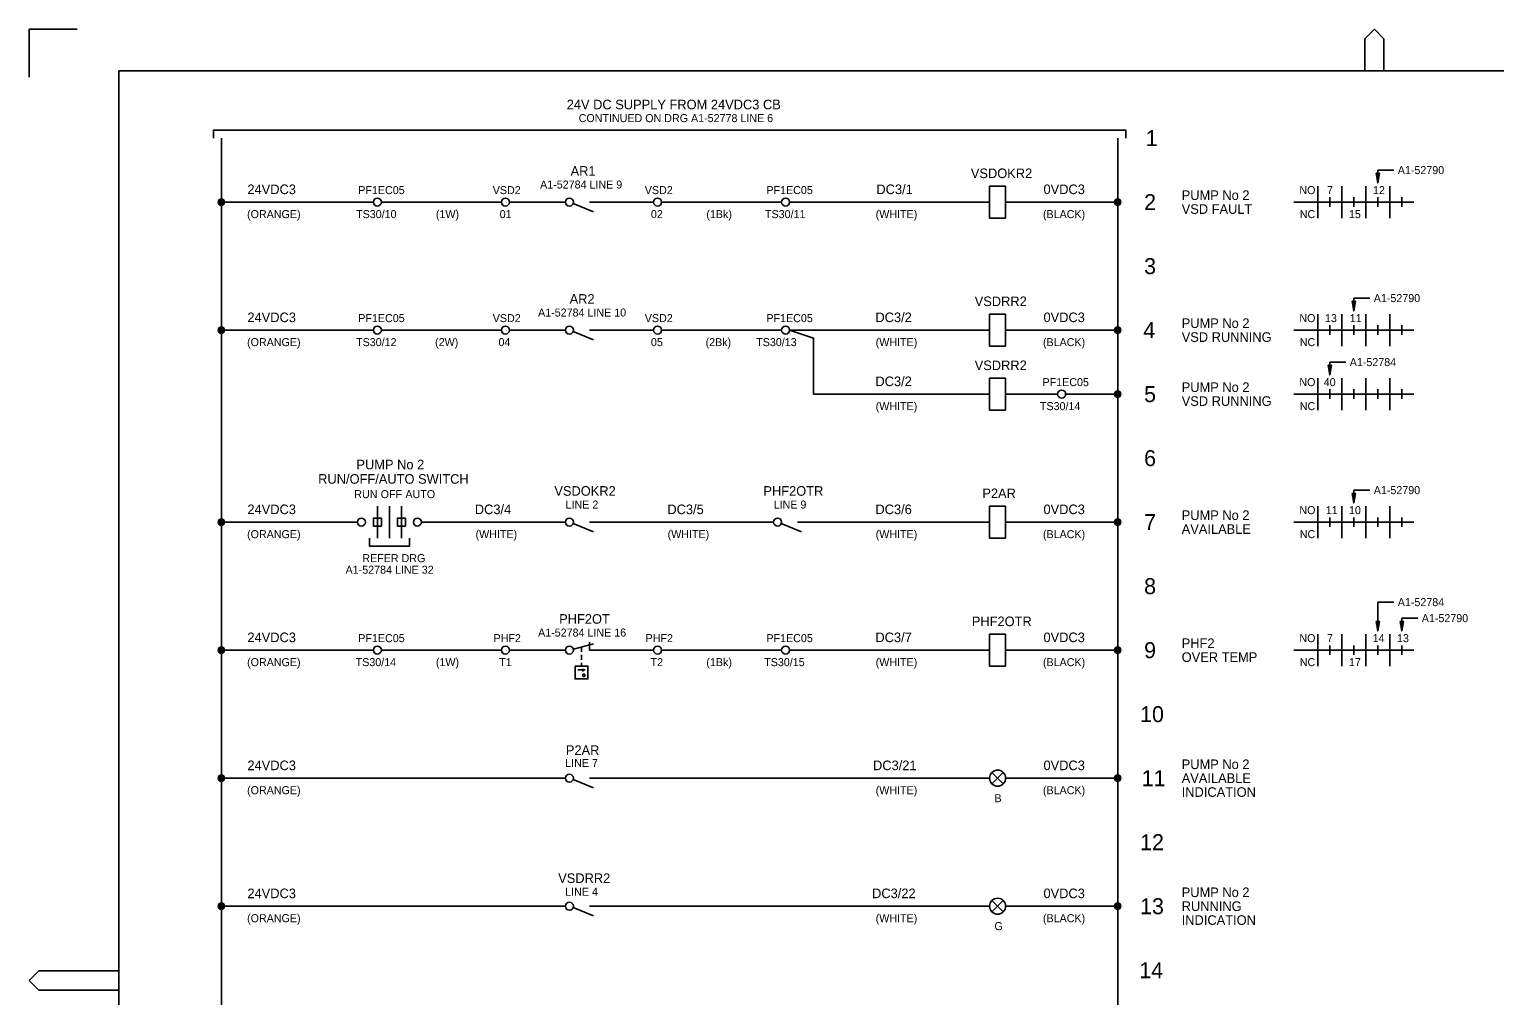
# Model space of a CAD drawing. Extents: x 0 to 841, y 0 to 594.
# Drawn here: x 0 to 457.8, y 292 to 594 of the extents above; entities that cross this region are included whole.
import ezdxf

# ---------------------------------------------------------------- set-up
doc = ezdxf.new("R2010")
doc.units = 0
for name, color, linetype in [('A1BORDER', 7, 'Continuous'), ('Level 1', 7, 'Continuous'), ('Level 10', 7, 'Continuous'), ('Level 5', 7, 'Continuous'), ('Level 6', 7, 'Continuous')]:
    doc.layers.add(name, color=color, linetype=linetype)

msp = doc.modelspace()

# ---------------------------------------------------------------- linework, layer by layer
at = {"layer": 'A1BORDER'}
for p, q in [((0, 594), (15, 594)), ((0, 579), (0, 594)), ((417.19, 591), (420.19, 594)), ((417.19, 581), (417.19, 591)), ((423.19, 591), (420.19, 594)), ((423.19, 581), (423.19, 591)), ((28, 581), (829, 581)), ((28, 581), (28, 15)), ((3, 299.76), (0, 296.76)), ((28, 299.76), (3, 299.76)), ((3, 293.76), (0, 296.76)), ((28, 293.76), (3, 293.76))]:
    msp.add_line(p, q, dxfattribs=at)
at = {"layer": 'Level 1'}
for p, q in [((60, 200), (60, 560)), ((340, 200), (340, 560)), ((402.5, 535), (402.5, 545)), ((410, 535), (410, 545)), ((417.5, 535), (417.5, 545)), ((425, 535), (425, 545)), ((406.25, 541.5), (406.25, 538.5)), ((413.75, 541.5), (413.75, 538.5)), ((421.25, 541.5), (421.25, 538.5)), ((428.75, 541.5), (428.75, 538.5)), ((60, 540), (107.5, 540)), ((147.5, 540), (110, 540)), ((167.5, 540), (150, 540)), ((167.5, 540), (167.5, 540)), ((175, 540), (177.5, 540)), ((177.5, 540), (177.5, 540)), ((195, 540), (177.5, 540)), ((235, 540), (197.5, 540)), ((305, 540), (340, 540)), ((395, 540), (432.5, 540)), ((402.5, 495), (402.5, 505)), ((410, 495), (410, 505)), ((417.5, 495), (417.5, 505)), ((425, 495), (425, 505)), ((60, 500), (107.5, 500)), ((147.5, 500), (110, 500)), ((167.5, 500), (150, 500)), ((167.5, 500), (167.5, 500)), ((175, 500), (177.5, 500)), ((177.5, 500), (177.5, 500)), ((195, 500), (177.5, 500)), ((235, 500), (197.5, 500)), ((305, 500), (340, 500)), ((395, 500), (432.5, 500)), ((406.25, 501.5), (406.25, 498.5)), ((413.75, 501.5), (413.75, 498.5)), ((421.25, 501.5), (421.25, 498.5)), ((428.75, 501.5), (428.75, 498.5)), ((402.5, 475), (402.5, 485)), ((406.25, 481.5), (406.25, 478.5)), ((410, 475), (410, 485)), ((413.75, 481.5), (413.75, 478.5)), ((417.5, 475), (417.5, 485)), ((421.25, 481.5), (421.25, 478.5)), ((425, 475), (425, 485)), ((428.75, 481.5), (428.75, 478.5)), ((321.25, 480), (305, 480)), ((323.75, 480), (340, 480)), ((395, 480), (432.5, 480)), ((108.75, 445), (108.75, 435)), ((112.5, 445), (112.5, 435)), ((116.25, 445), (116.25, 435)), ((402.5, 435), (402.5, 445)), ((410, 435), (410, 445)), ((417.5, 435), (417.5, 445)), ((425, 435), (425, 445)), ((102.5, 440), (60, 440)), ((167.5, 440), (122.5, 440)), ((167.5, 440), (167.5, 440)), ((175, 440), (177.5, 440)), ((232.5, 440), (177.5, 440)), ((177.5, 440), (177.5, 440)), ((232.5, 440), (232.5, 440)), ((240, 440), (242.5, 440)), ((242.5, 440), (242.5, 440)), ((305, 440), (340, 440)), ((395, 440), (432.5, 440)), ((406.25, 441.5), (406.25, 438.5)), ((413.75, 441.5), (413.75, 438.5)), ((421.25, 441.5), (421.25, 438.5)), ((428.75, 441.5), (428.75, 438.5)), ((402.5, 395), (402.5, 405)), ((410, 395), (410, 405)), ((417.5, 395), (417.5, 405)), ((425, 395), (425, 405)), ((60, 400), (107.5, 400)), ((147.5, 400), (110, 400)), ((167.5, 400), (150, 400)), ((167.5, 400), (167.5, 400)), ((172.5, 401), (172.5, 399.5)), ((172.5, 398.5), (172.5, 397)), ((175, 400), (177.5, 400)), ((195, 400), (177.5, 400)), ((177.5, 400), (177.5, 400)), ((235, 400), (197.5, 400)), ((305, 400), (340, 400)), ((395, 400), (432.5, 400)), ((406.25, 401.5), (406.25, 398.5)), ((413.75, 401.5), (413.75, 398.5)), ((421.25, 401.5), (421.25, 398.5)), ((428.75, 401.5), (428.75, 398.5)), ((172.5, 396), (172.5, 395)), ((60, 360), (167.5, 360)), ((167.5, 360), (167.5, 360)), ((175, 360), (177.5, 360)), ((177.5, 360), (177.5, 360)), ((305, 360), (340, 360)), ((60, 320), (167.5, 320)), ((167.5, 320), (167.5, 320)), ((175, 320), (177.5, 320)), ((177.5, 320), (177.5, 320)), ((305, 320), (340, 320))]:
    msp.add_line(p, q, dxfattribs=at)
for points in [[(57.5, 560), (57.5, 562.5), (342.5, 562.5), (342.5, 560)], [(237.5, 500), (245, 497.5), (245, 480), (300, 480)], [(106.25, 435), (106.25, 432.5), (118.75, 432.5), (118.75, 435)], [(173.63, 393.87), (171.37, 393.87)], [(172.88, 394.12), (172.88, 393.37)], [(172.88, 392.14), (172.92, 392.32), (173.06, 392.45), (173.26, 392.51), (173.44, 392.45), (173.57, 392.32), (173.63, 392.14), (173.57, 391.94), (173.44, 391.8), (173.26, 391.76), (173.06, 391.8), (172.92, 391.94), (172.88, 392.14)]]:
    msp.add_lwpolyline(points, dxfattribs=at)
for points in [[(107.5, 438.75), (110, 438.75), (110, 441.25), (107.5, 441.25)], [(115, 438.75), (117.5, 438.75), (117.5, 441.25), (115, 441.25)], [(170.5, 395), (170.5, 391), (174.5, 391), (174.5, 395)]]:
    msp.add_lwpolyline(points, close=True, dxfattribs=at)
at = {"layer": 'Level 10'}
for p, q in [((59.1, 540.44), (59.1, 539.56)), ((59.4, 540.8), (59.4, 539.2)), ((59.7, 540.95), (59.7, 539.05)), ((60, 541), (60, 539.01)), ((60.3, 540.95), (60.3, 539.05)), ((60.6, 540.8), (60.6, 539.2)), ((60.9, 540.44), (60.9, 539.56)), ((339.1, 540.44), (339.1, 539.56)), ((339.4, 540.8), (339.4, 539.2)), ((339.7, 540.95), (339.7, 539.05)), ((340, 541), (340, 539.01)), ((340.3, 540.95), (340.3, 539.05)), ((340.6, 540.8), (340.6, 539.2)), ((340.9, 540.44), (340.9, 539.56)), ((61, 540), (61, 540)), ((169.91, 539.54), (176.25, 537)), ((341, 540), (341, 540)), ((59.1, 500.44), (59.1, 499.56)), ((59.4, 500.8), (59.4, 499.2)), ((59.7, 500.95), (59.7, 499.05)), ((60, 501), (60, 499.01)), ((60.3, 500.95), (60.3, 499.05)), ((60.6, 500.8), (60.6, 499.2)), ((60.9, 500.44), (60.9, 499.56)), ((61, 500), (61, 500)), ((169.91, 499.54), (176.25, 497)), ((339.1, 500.44), (339.1, 499.56)), ((339.4, 500.8), (339.4, 499.2)), ((339.7, 500.95), (339.7, 499.05)), ((340, 501), (340, 499.01)), ((340.3, 500.95), (340.3, 499.05)), ((340.6, 500.8), (340.6, 499.2)), ((340.9, 500.44), (340.9, 499.56)), ((341, 500), (341, 500)), ((339.4, 480.8), (339.4, 479.2)), ((339.7, 480.95), (339.7, 479.05)), ((340, 481), (340, 479.01)), ((340.3, 480.95), (340.3, 479.05)), ((340.6, 480.8), (340.6, 479.2)), ((339.1, 480.44), (339.1, 479.56)), ((340.9, 480.44), (340.9, 479.56)), ((341, 480), (341, 480)), ((59.1, 440.44), (59.1, 439.56)), ((59.4, 440.8), (59.4, 439.2)), ((59.7, 440.95), (59.7, 439.05)), ((60, 441), (60, 439.01)), ((60.3, 440.95), (60.3, 439.05)), ((60.6, 440.8), (60.6, 439.2)), ((60.9, 440.44), (60.9, 439.56)), ((61, 440), (61, 440)), ((169.91, 439.54), (176.25, 437)), ((234.91, 439.54), (241.25, 437)), ((339.1, 440.44), (339.1, 439.56)), ((339.4, 440.8), (339.4, 439.2)), ((339.7, 440.95), (339.7, 439.05)), ((340, 441), (340, 439.01)), ((340.3, 440.95), (340.3, 439.05)), ((340.6, 440.8), (340.6, 439.2)), ((340.9, 440.44), (340.9, 439.56)), ((341, 440), (341, 440)), ((59.1, 400.44), (59.1, 399.56)), ((59.4, 400.8), (59.4, 399.2)), ((59.7, 400.95), (59.7, 399.05)), ((60, 401), (60, 399.01)), ((60.3, 400.95), (60.3, 399.05)), ((60.6, 400.8), (60.6, 399.2)), ((60.9, 400.44), (60.9, 399.56)), ((61, 400), (61, 400)), ((169.96, 400.32), (176.25, 402)), ((175, 402.5), (175, 400)), ((339.1, 400.44), (339.1, 399.56)), ((339.4, 400.8), (339.4, 399.2)), ((339.7, 400.95), (339.7, 399.05)), ((340, 401), (340, 399.01)), ((340.3, 400.95), (340.3, 399.05)), ((340.6, 400.8), (340.6, 399.2)), ((340.9, 400.44), (340.9, 399.56)), ((341, 400), (341, 400)), ((304.27, 361.77), (300.73, 358.23)), ((300.73, 361.77), (304.27, 358.23)), ((59.1, 360.44), (59.1, 359.56)), ((59.4, 360.8), (59.4, 359.2)), ((59.7, 360.95), (59.7, 359.05)), ((60, 361), (60, 359.01)), ((60.3, 360.95), (60.3, 359.05)), ((60.6, 360.8), (60.6, 359.2)), ((60.9, 360.44), (60.9, 359.56)), ((61, 360), (61, 360)), ((169.91, 359.54), (176.25, 357)), ((339.1, 360.44), (339.1, 359.56)), ((339.4, 360.8), (339.4, 359.2)), ((339.7, 360.95), (339.7, 359.05)), ((340, 361), (340, 359.01)), ((340.3, 360.95), (340.3, 359.05)), ((340.6, 360.8), (340.6, 359.2)), ((340.9, 360.44), (340.9, 359.56)), ((341, 360), (341, 360)), ((59.4, 320.8), (59.4, 319.2)), ((59.7, 320.95), (59.7, 319.05)), ((60, 321), (60, 319.01)), ((60.3, 320.95), (60.3, 319.05)), ((60.6, 320.8), (60.6, 319.2)), ((304.27, 321.77), (300.73, 318.23)), ((300.73, 321.77), (304.27, 318.23)), ((339.4, 320.8), (339.4, 319.2)), ((339.7, 320.95), (339.7, 319.05)), ((340, 321), (340, 319.01)), ((340.3, 320.95), (340.3, 319.05)), ((340.6, 320.8), (340.6, 319.2)), ((59.1, 320.44), (59.1, 319.56)), ((60.9, 320.44), (60.9, 319.56)), ((61, 320), (61, 320)), ((169.91, 319.54), (176.25, 317)), ((339.1, 320.44), (339.1, 319.56)), ((340.9, 320.44), (340.9, 319.56)), ((341, 320), (341, 320))]:
    msp.add_line(p, q, dxfattribs=at)
for points in [[(305, 545), (305, 535), (300, 535), (300, 545), (305, 545)], [(305, 505), (305, 495), (300, 495), (300, 505), (305, 505)], [(305, 485), (305, 475), (300, 475), (300, 485), (305, 485)], [(305, 445), (305, 435), (300, 435), (300, 445), (305, 445)], [(305, 405), (305, 395), (300, 395), (300, 405), (305, 405)]]:
    msp.add_lwpolyline(points, dxfattribs=at)
for centre, radius in [((60, 540), 1), ((168.75, 540), 1.25), ((340, 540), 1), ((60, 500), 1), ((168.75, 500), 1.25), ((340, 500), 1), ((340, 480), 1), ((60, 440), 1), ((168.75, 440), 1.25), ((233.75, 440), 1.25), ((340, 440), 1), ((60, 400), 1), ((168.75, 400), 1.25), ((340, 400), 1), ((302.5, 360), 2.5), ((60, 360), 1), ((168.75, 360), 1.25), ((340, 360), 1), ((60, 320), 1), ((168.75, 320), 1.25), ((302.5, 320), 2.5), ((340, 320), 1)]:
    msp.add_circle(centre, radius, dxfattribs=at)
at = {"layer": 'Level 5'}
for centre in [(108.75, 540), (148.75, 540), (196.25, 540), (236.25, 540), (108.75, 500), (148.75, 500), (196.25, 500), (236.25, 500), (322.5, 480), (103.75, 440), (121.25, 440), (108.75, 400), (148.75, 400), (196.25, 400), (236.25, 400)]:
    msp.add_circle(centre, 1.25, dxfattribs=at)
at = {"layer": 'Level 6'}
for p, q in [((421.25, 546.5), (421.25, 550)), ((421.25, 550), (426.25, 550)), ((237.5, 540), (300, 540)), ((413.75, 506.5), (413.75, 510)), ((413.75, 510), (418.75, 510)), ((237.5, 500), (300, 500)), ((406.25, 486.5), (406.25, 490)), ((406.25, 490), (411.25, 490)), ((413.75, 446.5), (413.75, 450)), ((413.75, 450), (418.75, 450)), ((242.5, 440), (300, 440)), ((421.25, 406.5), (421.25, 415)), ((421.25, 415), (426.25, 415)), ((428.75, 406.5), (428.75, 410)), ((428.75, 410), (433.75, 410)), ((237.5, 400), (300, 400)), ((177.5, 360), (300, 360)), ((177.5, 320), (300, 320))]:
    msp.add_line(p, q, dxfattribs=at)
for points in [[(420.75, 549), (421.25, 546), (421.75, 549)], [(413.25, 509), (413.75, 506), (414.25, 509)], [(405.75, 489), (406.25, 486), (406.75, 489)], [(413.25, 449), (413.75, 446), (414.25, 449)], [(420.75, 409), (421.25, 406), (421.75, 409)], [(428.25, 409), (428.75, 406), (429.25, 409)]]:
    msp.add_lwpolyline(points, close=True, dxfattribs=at)

# ---------------------------------------------------------------- texts
at = {"layer": 'Level 1'}
for s, height, p in [('24V DC SUPPLY FROM 24VDC3 CB', 3, (167.88, 569)), ('CONTINUED ON DRG A1-52778 LINE 6', 2.5, (171.61, 565)), ('1', 5, (348.75, 557.5)), ('PF1EC05', 2.5, (102.77, 542.5)), ('VSD2', 2.5, (144.77, 542.5)), ('VSD2', 2.5, (192.27, 542.5)), ('PF1EC05', 2.5, (230.27, 542.5)), ('NO', 2.5, (396.76, 542.5)), ('7', 2.5, (405.38, 542.5)), ('12', 2.5, (419.76, 542.5)), ('2', 5, (348.26, 537.5)), ('NC', 2.5, (396.88, 535)), ('15', 2.5, (412.26, 535)), ('3', 5, (348.26, 517.5)), ('PF1EC05', 2.5, (102.77, 502.5)), ('VSD2', 2.5, (144.77, 502.5)), ('VSD2', 2.5, (192.27, 502.5)), ('PF1EC05', 2.5, (230.27, 502.5)), ('NO', 2.5, (396.76, 502.5)), ('13', 2.5, (404.76, 502.5)), ('11', 2.5, (412.5, 502.5)), ('4', 5, (348.01, 497.5)), ('NC', 2.5, (396.88, 495)), ('PF1EC05', 2.5, (316.52, 482.5)), ('5', 5, (348.26, 477.5)), ('NO', 2.5, (396.76, 482.5)), ('40', 2.5, (404.38, 482.5)), ('NC', 2.5, (396.88, 475)), ('6', 5, (348.26, 457.5)), ('PUMP No 2', 3, (102.19, 456.5)), ('RUN/OFF/AUTO SWITCH', 3, (90.24, 452)), ('RUN', 2.5, (101.52, 447.5)), ('OFF', 2.5, (109.76, 447.5)), ('AUTO', 2.5, (117.5, 447.5)), ('NO', 2.5, (396.76, 442.5)), ('11', 2.5, (405.01, 442.5)), ('10', 2.5, (412.26, 442.5)), ('7', 5, (348.26, 437.5)), ('NC', 2.5, (396.88, 435)), ('A1-52784 LINE 32', 2.5, (98.8, 423.88)), ('REFER DRG', 2.5, (104.03, 427.5)), ('8', 5, (348.26, 417.5)), ('PF1EC05', 2.5, (102.77, 402.5)), ('PHF2', 2.5, (145.02, 402.5)), ('PHF2', 2.5, (192.52, 402.5)), ('PF1EC05', 2.5, (230.27, 402.5)), ('NO', 2.5, (396.76, 402.5)), ('7', 2.5, (405.38, 402.5)), ('14', 2.5, (419.63, 402.5)), ('13', 2.5, (427.26, 402.5)), ('9', 5, (348.26, 397.5)), ('NC', 2.5, (396.88, 395)), ('17', 2.5, (412.26, 395)), ('10', 5, (347.01, 377.5)), ('11', 5, (347.51, 357.5)), ('12', 5, (347.01, 337.5)), ('13', 5, (347.01, 317.5)), ('14', 5, (346.76, 297.5))]:
    msp.add_text(s, height=height, dxfattribs=at).set_placement(p)
at = {"layer": 'Level 5'}
for s, height, p in [('AR1', 3, (169.1, 548.25)), ('VSDOKR2', 3, (294.13, 547.5)), ('A1-52790', 2.5, (427.5, 548.75)), ('24VDC3', 3, (68.13, 542.5)), ('A1-52784 LINE 9', 2.5, (159.57, 544.25)), ('DC3/1', 3, (264.62, 542.5)), ('0VDC3', 3, (316.82, 542.5)), ('PUMP No 2', 3, (360, 540.67)), ('(ORANGE)', 2.5, (68.03, 535)), ('TS30/10', 2.5, (102.08, 535)), ('(1W)', 2.5, (127.01, 535)), ('01', 2.5, (146.94, 535)), ('02', 2.5, (194.19, 535)), ('(1Bk)', 2.5, (211.51, 535)), ('TS30/11', 2.5, (229.83, 535)), ('(WHITE)', 2.5, (264.4, 535)), ('(BLACK)', 2.5, (316.65, 535)), ('VSD FAULT', 3, (360, 536.33)), ('AR2', 3, (168.8, 508.25)), ('VSDRR2', 3, (295.33, 507.5)), ('A1-52790', 2.5, (420, 508.75)), ('24VDC3', 3, (68.13, 502.5)), ('A1-52784 LINE 10', 2.5, (158.94, 504.25)), ('DC3/2', 3, (264.32, 502.5)), ('0VDC3', 3, (316.82, 502.5)), ('PUMP No 2', 3, (360, 500.67)), ('VSD RUNNING', 3, (360, 496.33)), ('(ORANGE)', 2.5, (68.03, 495)), ('TS30/12', 2.5, (102.08, 495)), ('(2W)', 2.5, (126.76, 495)), ('04', 2.5, (146.57, 495)), ('05', 2.5, (194.19, 495)), ('(2Bk)', 2.5, (211.26, 495)), ('TS30/13', 2.5, (227.08, 495)), ('(WHITE)', 2.5, (264.4, 495)), ('(BLACK)', 2.5, (316.65, 495)), ('VSDRR2', 3, (295.33, 487.5)), ('A1-52784', 2.5, (412.5, 488.75)), ('DC3/2', 3, (264.32, 482.5)), ('PUMP No 2', 3, (360, 480.67)), ('(WHITE)', 2.5, (264.4, 475)), ('TS30/14', 2.5, (315.71, 475)), ('VSD RUNNING', 3, (360, 476.33)), ('VSDOKR2', 3, (164.02, 448.25)), ('PHF2OTR', 3, (229.32, 448.25)), ('P2AR', 3, (297.72, 447.5)), ('A1-52790', 2.5, (420, 448.75)), ('24VDC3', 3, (68.13, 442.5)), ('DC3/4', 3, (139.17, 442.5)), ('LINE 2', 2.5, (167.53, 444.25)), ('DC3/5', 3, (199.32, 442.5)), ('LINE 9', 2.5, (232.53, 444.25)), ('DC3/6', 3, (264.32, 442.5)), ('0VDC3', 3, (316.82, 442.5)), ('PUMP No 2', 3, (360, 440.67)), ('(ORANGE)', 2.5, (68.03, 435)), ('(WHITE)', 2.5, (139.4, 435)), ('(WHITE)', 2.5, (199.4, 435)), ('(WHITE)', 2.5, (264.4, 435)), ('(BLACK)', 2.5, (316.65, 435)), ('AVAILABLE', 3, (360, 436.33)), ('A1-52784', 2.5, (427.5, 413.75)), ('PHF2OT', 3, (165.52, 408.25)), ('PHF2OTR', 3, (294.43, 407.5)), ('A1-52790', 2.5, (435, 408.75)), ('24VDC3', 3, (68.13, 402.5)), ('A1-52784 LINE 16', 2.5, (158.94, 404.25)), ('DC3/7', 3, (264.32, 402.5)), ('0VDC3', 3, (316.82, 402.5)), ('PHF2', 3, (360, 400.67)), ('OVER TEMP', 3, (360, 396.33)), ('(ORANGE)', 2.5, (68.03, 395)), ('TS30/14', 2.5, (101.96, 395)), ('(1W)', 2.5, (127.01, 395)), ('T1', 2.5, (146.81, 395)), ('T2', 2.5, (194.07, 395)), ('(1Bk)', 2.5, (211.51, 395)), ('TS30/15', 2.5, (229.58, 395)), ('(WHITE)', 2.5, (264.4, 395)), ('(BLACK)', 2.5, (316.65, 395)), ('P2AR', 3, (167.61, 367.25)), ('24VDC3', 3, (68.13, 362.5)), ('LINE 7', 2.5, (167.41, 363.5)), ('DC3/21', 3, (263.58, 362.5)), ('0VDC3', 3, (316.82, 362.5)), ('PUMP No 2', 3, (360, 362.84)), ('(ORANGE)', 2.5, (68.03, 355)), ('(WHITE)', 2.5, (264.4, 355)), ('(BLACK)', 2.5, (316.65, 355)), ('AVAILABLE', 3, (360, 358.5)), ('INDICATION', 3, (360, 354.16)), ('B', 2.5, (301.5, 352.5)), ('VSDRR2', 3, (165.22, 327.25)), ('24VDC3', 3, (68.13, 322.5)), ('LINE 4', 2.5, (167.41, 323.25)), ('DC3/22', 3, (263.28, 322.5)), ('0VDC3', 3, (316.82, 322.5)), ('PUMP No 2', 3, (360, 322.84)), ('RUNNING', 3, (360, 318.5)), ('(ORANGE)', 2.5, (68.03, 315)), ('(WHITE)', 2.5, (264.4, 315)), ('(BLACK)', 2.5, (316.65, 315)), ('INDICATION', 3, (360, 314.16)), ('G', 2.5, (301.5, 312.5))]:
    msp.add_text(s, height=height, dxfattribs=at).set_placement(p)

doc.saveas('drawing.dxf')
